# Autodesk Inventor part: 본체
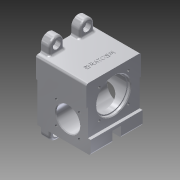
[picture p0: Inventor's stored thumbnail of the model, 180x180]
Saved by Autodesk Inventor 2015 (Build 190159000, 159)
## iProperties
Created: 2024-11
Part Number: 본체
Material: 알루미늄 6061
Document SubType Name: Modeling
Designer: 102-5
Density: 2.7 g/cm^3
Appearance: 알루미늄 - 평지
Mass: 803.29 g
Surface Area: 539.922 cm^2
Volume: 297.515 cm^3
Author: 102-5
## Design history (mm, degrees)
sketch "스케치1"
  geometry: L1 (-38, 33)-(38, 33); L2 (38, 33)-(38, -52); L3 (38, -52)-(-38, -52); L4 (-38, -52)-(-38, 33); 2 further points
  constraints: 8 end point, 2 parallel, 1 horizontal, 1 midpoint, 1 perpendicular, 1 vertical alignment
  dimensions: "d0" = 76 distance between parallel lines of L2 L4; "d1" = 85 distance between parallel lines of L3 L1; "d2" = 33 distance from line of point (0, 0) L1
extrude "돌출1" new body sketch "스케치1" distance "d3" = 74; taper "d4" = 0 deg
sketch "스케치2"
  geometry: L1 (-33, -38)-(52, -38) reference; L2 (52, -38)-(52, 38) reference; L3 (-4, -38)-(52, -38); L4 (52, -38)-(52, -36); L5 (52, -36)-(-4, -36); L6 (-4, -36)-(-4, -38); 1 further point
  constraints: 8 end point, 2 parallel, 2 point on line, 1 horizontal, 1 perpendicular
  dimensions: "d5" = 2 distance between parallel lines of L5 L1; "d6" = 56 distance between parallel lines of L2 L6
extrude "돌출2" cut sketch "스케치2" stored distance "d7" = 74; taper "d8" = 0 deg
sketch "스케치4"
  geometry: L1 (0, -52)-(-74, -52) reference; L2 (-74, -52)-(-74, 33) reference; L3 (-74, 33)-(0, 33) reference; L4 (0, 33)-(0, -52) reference; L5 (0, 33)-(-74, 33) reference; L6 (-74, -52)-(-74, 4) reference; L7 (-70, 33)-(-74, 33); L8 (-74, 33)-(-74, -33); L9 (-74, -33)-(-70, -33); L10 (-70, -33)-(-70, 33); 1 further point
  constraints: 8 end point, 2 parallel, 2 point on line, 1 horizontal, 1 perpendicular
  dimensions: "d9" = 4 distance between parallel lines of L2 L10; "d10" = 66 distance between parallel lines of L9 L3
extrude "돌출3" cut sketch "스케치4" stored distance "d11" = 4 (= d9); taper "d12" = 0 deg
sketch "스케치5"
  geometry: L1 (33, -38)-(33, 38) reference; L2 (53, 21)-(-72, 21); L3 (43, 31)-(-62, 31); L4 (-62, 11)-(43, 11); A1 r 10 centre (43, 21) between (43, 11) and (43, 31); A2 r 10 centre (-62, 21) between (-62, 31) and (-62, 11); 2 further points
  constraints: 8 end point, 6 point on circle, 4 tangent, 2 centre point, 2 point on line, 1 horizontal, 1 midpoint, 1 parallel
  dimensions: "d15" = 10 radius of A1; "d16" = 21 vertical distance of point (0, 0) A1.centre; "d17" = 105 distance of A2.centre A1.centre; "d18" = 10 distance from line of L1 A1.centre
extrude "돌출4" join sketch "스케치5" distance "d19" = 12; taper "d20" = 0 deg
sketch "스케치6"
  geometry: A1 r 10 centre (-43, 21) between (-43, 31) and (-43, 11) reference; 1 further point
hole "구멍1" sketch "스케치6" at (-43, 21) diameter "d21" = 6.6; stored, may be unused: countersink angle "d25" = 90 deg, drill point angle "d27" = 118 deg; dims "d22" = 6, "d23" = 11, "d24" = 6.6, "d26" = 8
sketch "스케치7"
  geometry: A1 r 10 centre (62, 21) between (62, 11) and (62, 31) reference; 1 further point
hole "구멍2" sketch "스케치7" at (62, 21) diameter "d28" = 6.6; stored, may be unused: countersink angle "d32" = 90 deg, drill point angle "d34" = 118 deg; dims "d29" = 6, "d30" = 11, "d31" = 6.6, "d33" = 8
sketch "스케치8"
  geometry: L1 (0, 0)-(0, 56) reference; L2 (0, 85)-(70, 85) reference; C1 r 16.5 at (42, 28); 1 further point
  constraints: 1 centre point
  dimensions: "d35" = 33 diameter of C1; "d36" = 42 distance from line of C1.centre L1; "d37" = 57 distance from line of C1.centre L2
extrude "돌출5" cut sketch "스케치8" stored distance "d38" = 12; taper "d39" = 0 deg
sketch "스케치9"
  geometry: L1 (42, 28)-(58.5, 28); L2 (42, 28)-(58, 44); 2 further points
  constraints: 4 end point, 1 coincident, 1 horizontal, 1 horizontal alignment, 1 other
  dimensions: "d40" = 45 deg angle of L2 L1; "d42" = 16 horizontal distance of point (58, 44) L1.start
hole "구멍3" sketch "스케치9" at (58, 44) diameter "d43" = 3.242; stored, may be unused: countersink angle "d47" = 90 deg, drill point angle "d49" = 118 deg; dims "d44" = 8, "d45" = 11, "d46" = 6.6, "d48" = 10
sketch "스케치10"
  geometry: L1 (52, -36)-(52, 36) reference; L2 (69.046, -6)-(37, -6); L3 (37, -6)-(37, 6); L4 (37, 6)-(69.046, 6); L5 (69.046, 6)-(69.046, -6); 2 further points
  constraints: 8 end point, 2 parallel, 1 horizontal, 1 horizontal alignment, 1 midpoint, 1 perpendicular
  dimensions: "d53" = 12 distance between parallel lines of L4 L2; "d54" = 15 distance between parallel lines of L1 L3; "d55" = 32.04603 distance between parallel lines of L5 L3
extrude "돌출6" cut sketch "스케치10" stored distance "d56" = 12; taper "d57" = 0 deg
sketch "스케치11"
  geometry: C1 r 23.5 at (33, 38); 1 further point
  constraints: 1 centre point, 1 coincident
  dimensions: "d58" = 47 diameter of C1
extrude "돌출7" cut sketch "스케치11" distance "d59" = 4; taper "d60" = 0 deg
sketch "스케치12"
  geometry: C1 r 23.5 at (0, 0) reference; C2 r 22 at (0, 0)
  constraints: 1 centre point, 1 coincident
  dimensions: "d61" = 44 diameter of C2
extrude "돌출8" cut sketch "스케치12" distance "d62" = 48; taper "d63" = 0 deg
sketch "스케치13"
  geometry: C1 r 22 at (0, 0) reference; C2 r 17.5 at (0, 0)
  constraints: 1 centre point, 1 coincident
  dimensions: "d64" = 35 diameter of C2
extrude "돌출9" cut sketch "스케치13" distance "d65" = 11; taper "d66" = 0 deg
sketch "스케치14"
  geometry: C1 r 17.5 at (0, 0) reference; C2 r 15 at (0, 0)
  constraints: 1 centre point, 1 coincident
  dimensions: "d67" = 30 diameter of C2
extrude "돌출10" cut sketch "스케치14" distance "d68" = 3; taper "d69" = 0 deg
fillet "모깎기1" dims "d70" = 3
fillet "모깎기2" dims "d71" = 0.6
chamfer "모따기1" distance "d72" = 1; stored, may be unused: second distance "d73" = 2, angle "d74" = 45 deg
fillet "모깎기3" dims "d75" = 3
chamfer "모따기2" distance "d76" = 1; stored, may be unused: second distance "d77" = 2, angle "d78" = 45 deg
sketch "스케치15"
  geometry: L1 (33, 38)-(12.847, 58.153); L2 (33, 38)-(4.5, 38); C1 r 24.5 at (33, 38) reference; A1 r 28.5 centre (33, 38) between (12.847, 58.153) and (4.5, 38)
  constraints: 4 end point, 2 point on circle, 1 centre point, 1 coincident, 1 horizontal
  dimensions: "d79" = 57 diameter of A1; "d81" = 45 deg angle of L1 L2
hole "구멍4" sketch "스케치15" at (12.847, 58.153) diameter "d82" = 3.242; stored, may be unused: countersink angle "d86" = 90 deg, drill point angle "d88" = 118 deg; dims "d83" = 8, "d84" = 11, "d85" = 6.6, "d87" = 10
sketch "스케치16"
  geometry: L1 (0, 0)-(0, 12) reference; L2 (74, 12)-(74, 0) reference; 4 further points
  constraints: 2 horizontal alignment, 1 midpoint
  dimensions: "d92" = 40 distance of point (12, 6) point (52, 6); "d93" = 12 distance from line of point (12, 6) L1
hole "구멍5" sketch "스케치16" at (12, 6), (52, 6) diameter "d94" = 3.242; stored, may be unused: countersink angle "d98" = 90 deg, drill point angle "d100" = 118 deg; dims "d95" = 8, "d96" = 11, "d97" = 6.6, "d99" = 10
fillet "모깎기4" dims "d101" = 3
fillet "모깎기5" dims "d102" = 3
fillet "모깎기6" dims "d103" = 3
sketch "스케치17"
  geometry: L1 (0, 0)-(0, 16) reference; L2 (70, -27)-(70, 43) reference; 3 further points
  constraints: 1 horizontal alignment, 1 midpoint, 1 other
  dimensions: "d105" = 20 distance from line of L2 point (50, 8)
feature "엠보싱1" sketch "스케치17" dims "d106" = 0.5, "d107" = 0
chamfer "모따기3" distance "d108" = 1; stored, may be unused: second distance "d109" = 2, angle "d110" = 45 deg
fillet "모깎기8" dims "d111" = 3
chamfer "모따기4" distance "d112" = 1; stored, may be unused: second distance "d113" = 2, angle "d114" = 45 deg
node "솔리드1"
mirror "대칭1"
mirror "대칭2"
pattern_circular "원형 패턴1" dims angle "d51" = 360 deg
mirror "대칭3"
pattern_circular "원형 패턴2" dims angle "d90" = 360 deg
node "절단 모서리 투영1"
other parameters: "d80" = 45 deg
